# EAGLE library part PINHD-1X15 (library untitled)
PIN HEADER
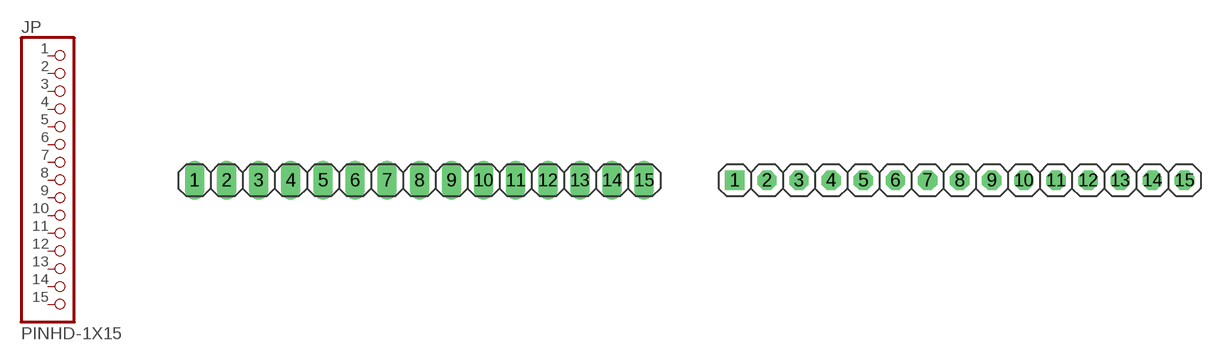
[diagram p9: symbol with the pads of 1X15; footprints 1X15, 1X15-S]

Designator prefix JP

## PINHD-1X15_2.54  [1X15]
1  1  pas
2  2  pas
3  3  pas
4  4  pas
5  5  pas
6  6  pas
7  7  pas
8  8  pas
9  9  pas
10  10  pas
11  11  pas
12  12  pas
13  13  pas
14  14  pas
15  15  pas

## PINHD-1X15_2.54-S  [1X15-S]
Pads as for 1X15

## PINHD-1X15_2.54-90°  [1X15/90]
Pads as for 1X15

## PINHD-1X15_2.54-90°-S  [1X15/90-S]
Pads as for 1X15

## PINHD-1X15_2.00  [1X15M]
Pads as for 1X15

## PINHD-1X15_2.54-SMD  [1X15SMD]
Pads as for 1X15

## PINHD-1X15_2.54-SMD-90°  [1X15SMD/90]
Pads as for 1X15

## Footprint 1X15 (pad centres in mm)
PIN HEADER - 2.54
drill 1.016 long: 1 -17.78,0; 2 -15.24,0; 3 -12.7,0; 4 -10.16,0; 5 -7.62,0; 6 -5.08,0; 7 -2.54,0; 8 0,0; 9 2.54,0; 10 5.08,0; 11 7.62,0; 12 10.16,0; 13 12.7,0; 14 15.24,0; 15 17.78,0

## Footprint 1X15-S (pad centres in mm)
PIN HEADER - 2.54
drill 1.016 square: 1 -17.78,0
drill 1.016 octagon: 2 -15.24,0; 3 -12.7,0; 4 -10.16,0; 5 -7.62,0; 6 -5.08,0; 7 -2.54,0; 8 0,0; 9 2.54,0; 10 5.08,0; 11 7.62,0; 12 10.16,0; 13 12.7,0; 14 15.24,0; 15 17.78,0

## Footprint 1X15/90 (pad centres in mm)
PIN HEADER - 2.54 90°
drill 1.016 long: 1 -17.78,-3.81; 2 -15.24,-3.81; 3 -12.7,-3.81; 4 -10.16,-3.81; 5 -7.62,-3.81; 6 -5.08,-3.81; 7 -2.54,-3.81; 8 0,-3.81; 9 2.54,-3.81; 10 5.08,-3.81; 11 7.62,-3.81; 12 10.16,-3.81; 13 12.7,-3.81; 14 15.24,-3.81; 15 17.78,-3.81

## Footprint 1X15/90-S (pad centres in mm)
PIN HEADER - 2.54 90°
drill 1.016 square: 1 -17.78,-3.81
drill 1.016 octagon: 2 -15.24,-3.81; 3 -12.7,-3.81; 4 -10.16,-3.81; 5 -7.62,-3.81; 6 -5.08,-3.81; 7 -2.54,-3.81; 8 0,-3.81; 9 2.54,-3.81; 10 5.08,-3.81; 11 7.62,-3.81; 12 10.16,-3.81; 13 12.7,-3.81; 14 15.24,-3.81; 15 17.78,-3.81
